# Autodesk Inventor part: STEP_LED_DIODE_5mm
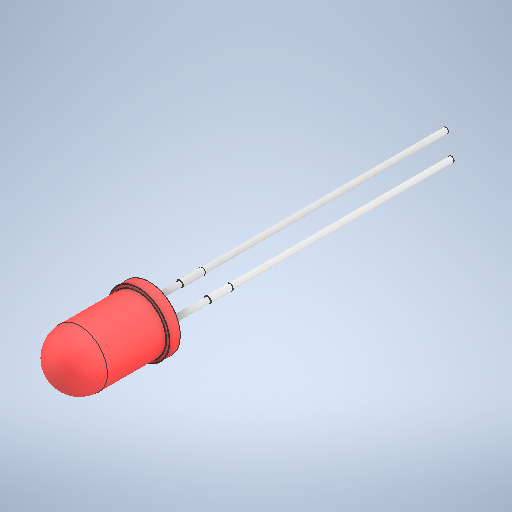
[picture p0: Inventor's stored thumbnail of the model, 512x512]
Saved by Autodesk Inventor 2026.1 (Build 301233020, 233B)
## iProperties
Created: 2024-12
Part Number: STEP_LED_DIODE_5mm
Material: Steel
Document SubType Name: Modeling
Designer: hp
Density: 7.85 g/cm^3
Appearance: Default
Title: STEP_DIODE_5mm v4.step
Sending System: Autodesk Translation Framework v13.20.0.188
Preprocessor: ST-DEVELOPER v20
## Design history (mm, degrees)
feature "LED DIODE CAP"
feature "LED FILAMENT"
feature "LED LEGS"
body "Solid1"
body "Solid2"
body "Solid3"
